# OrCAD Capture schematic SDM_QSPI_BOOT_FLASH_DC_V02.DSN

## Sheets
1 Cover: title: SDM QSPI Boot Flash Daughter Card; rev: 0.1; note: 150-0330636-A1     (6XX-44489R)
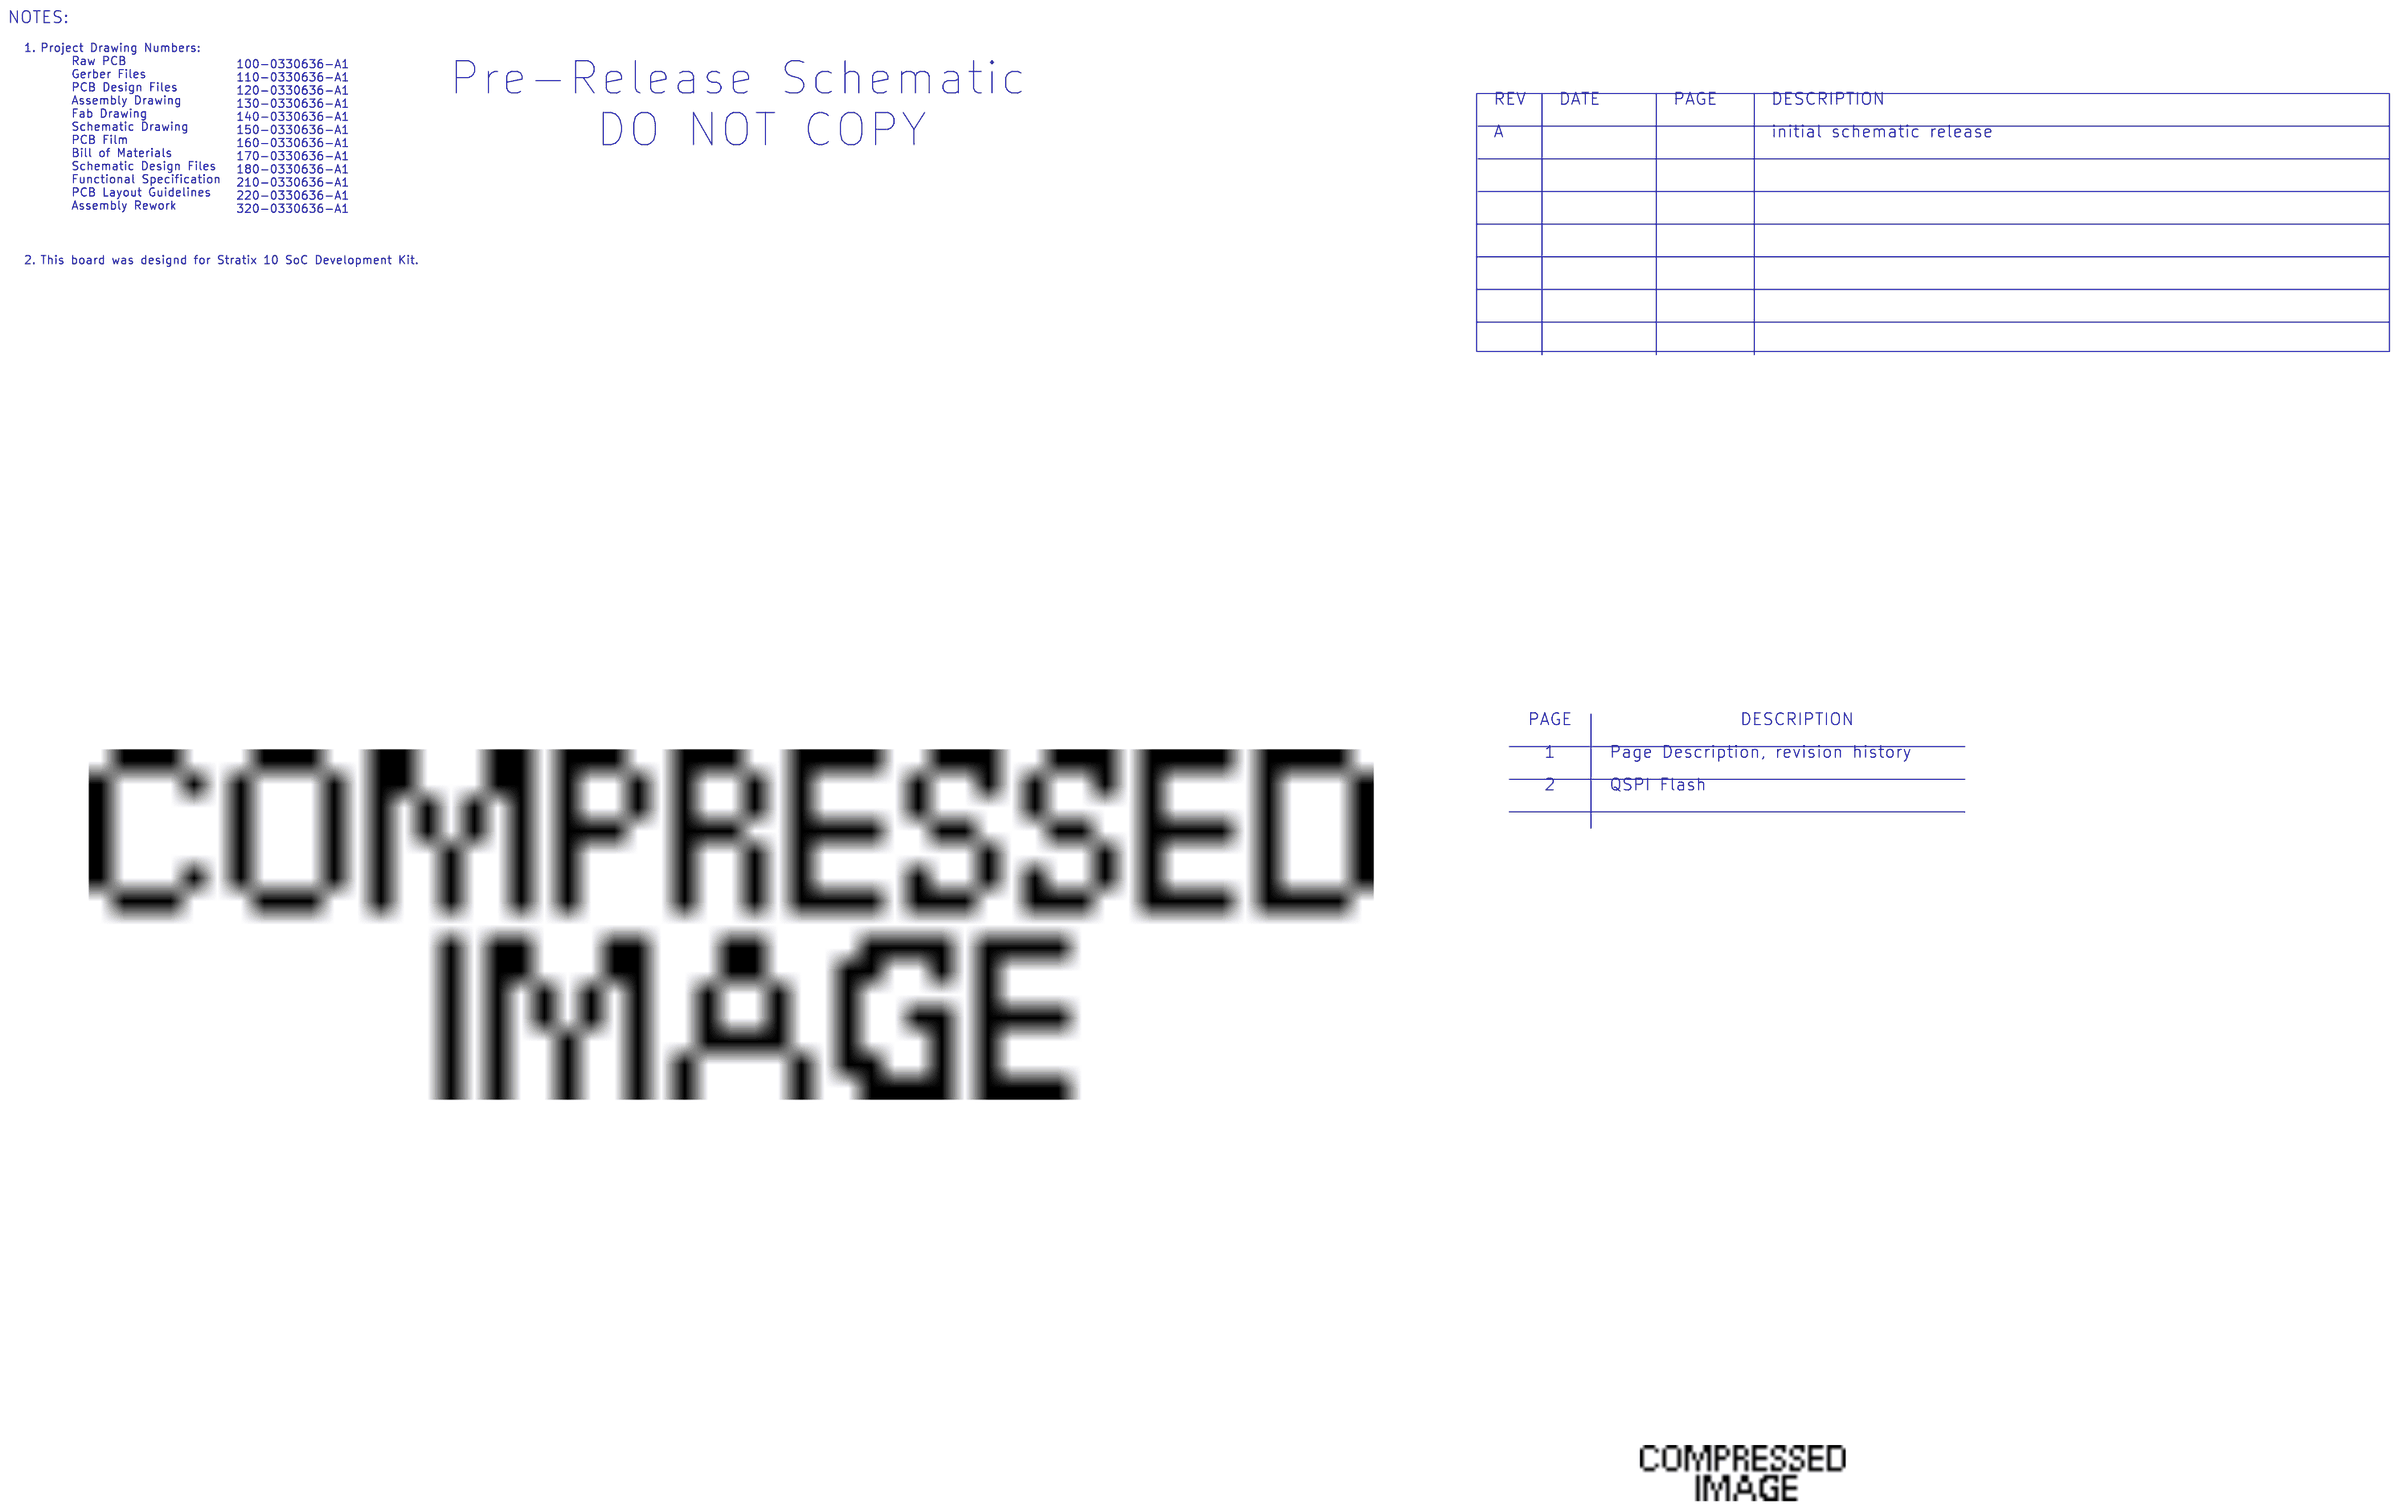
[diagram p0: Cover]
2 QSPI Flash: size B
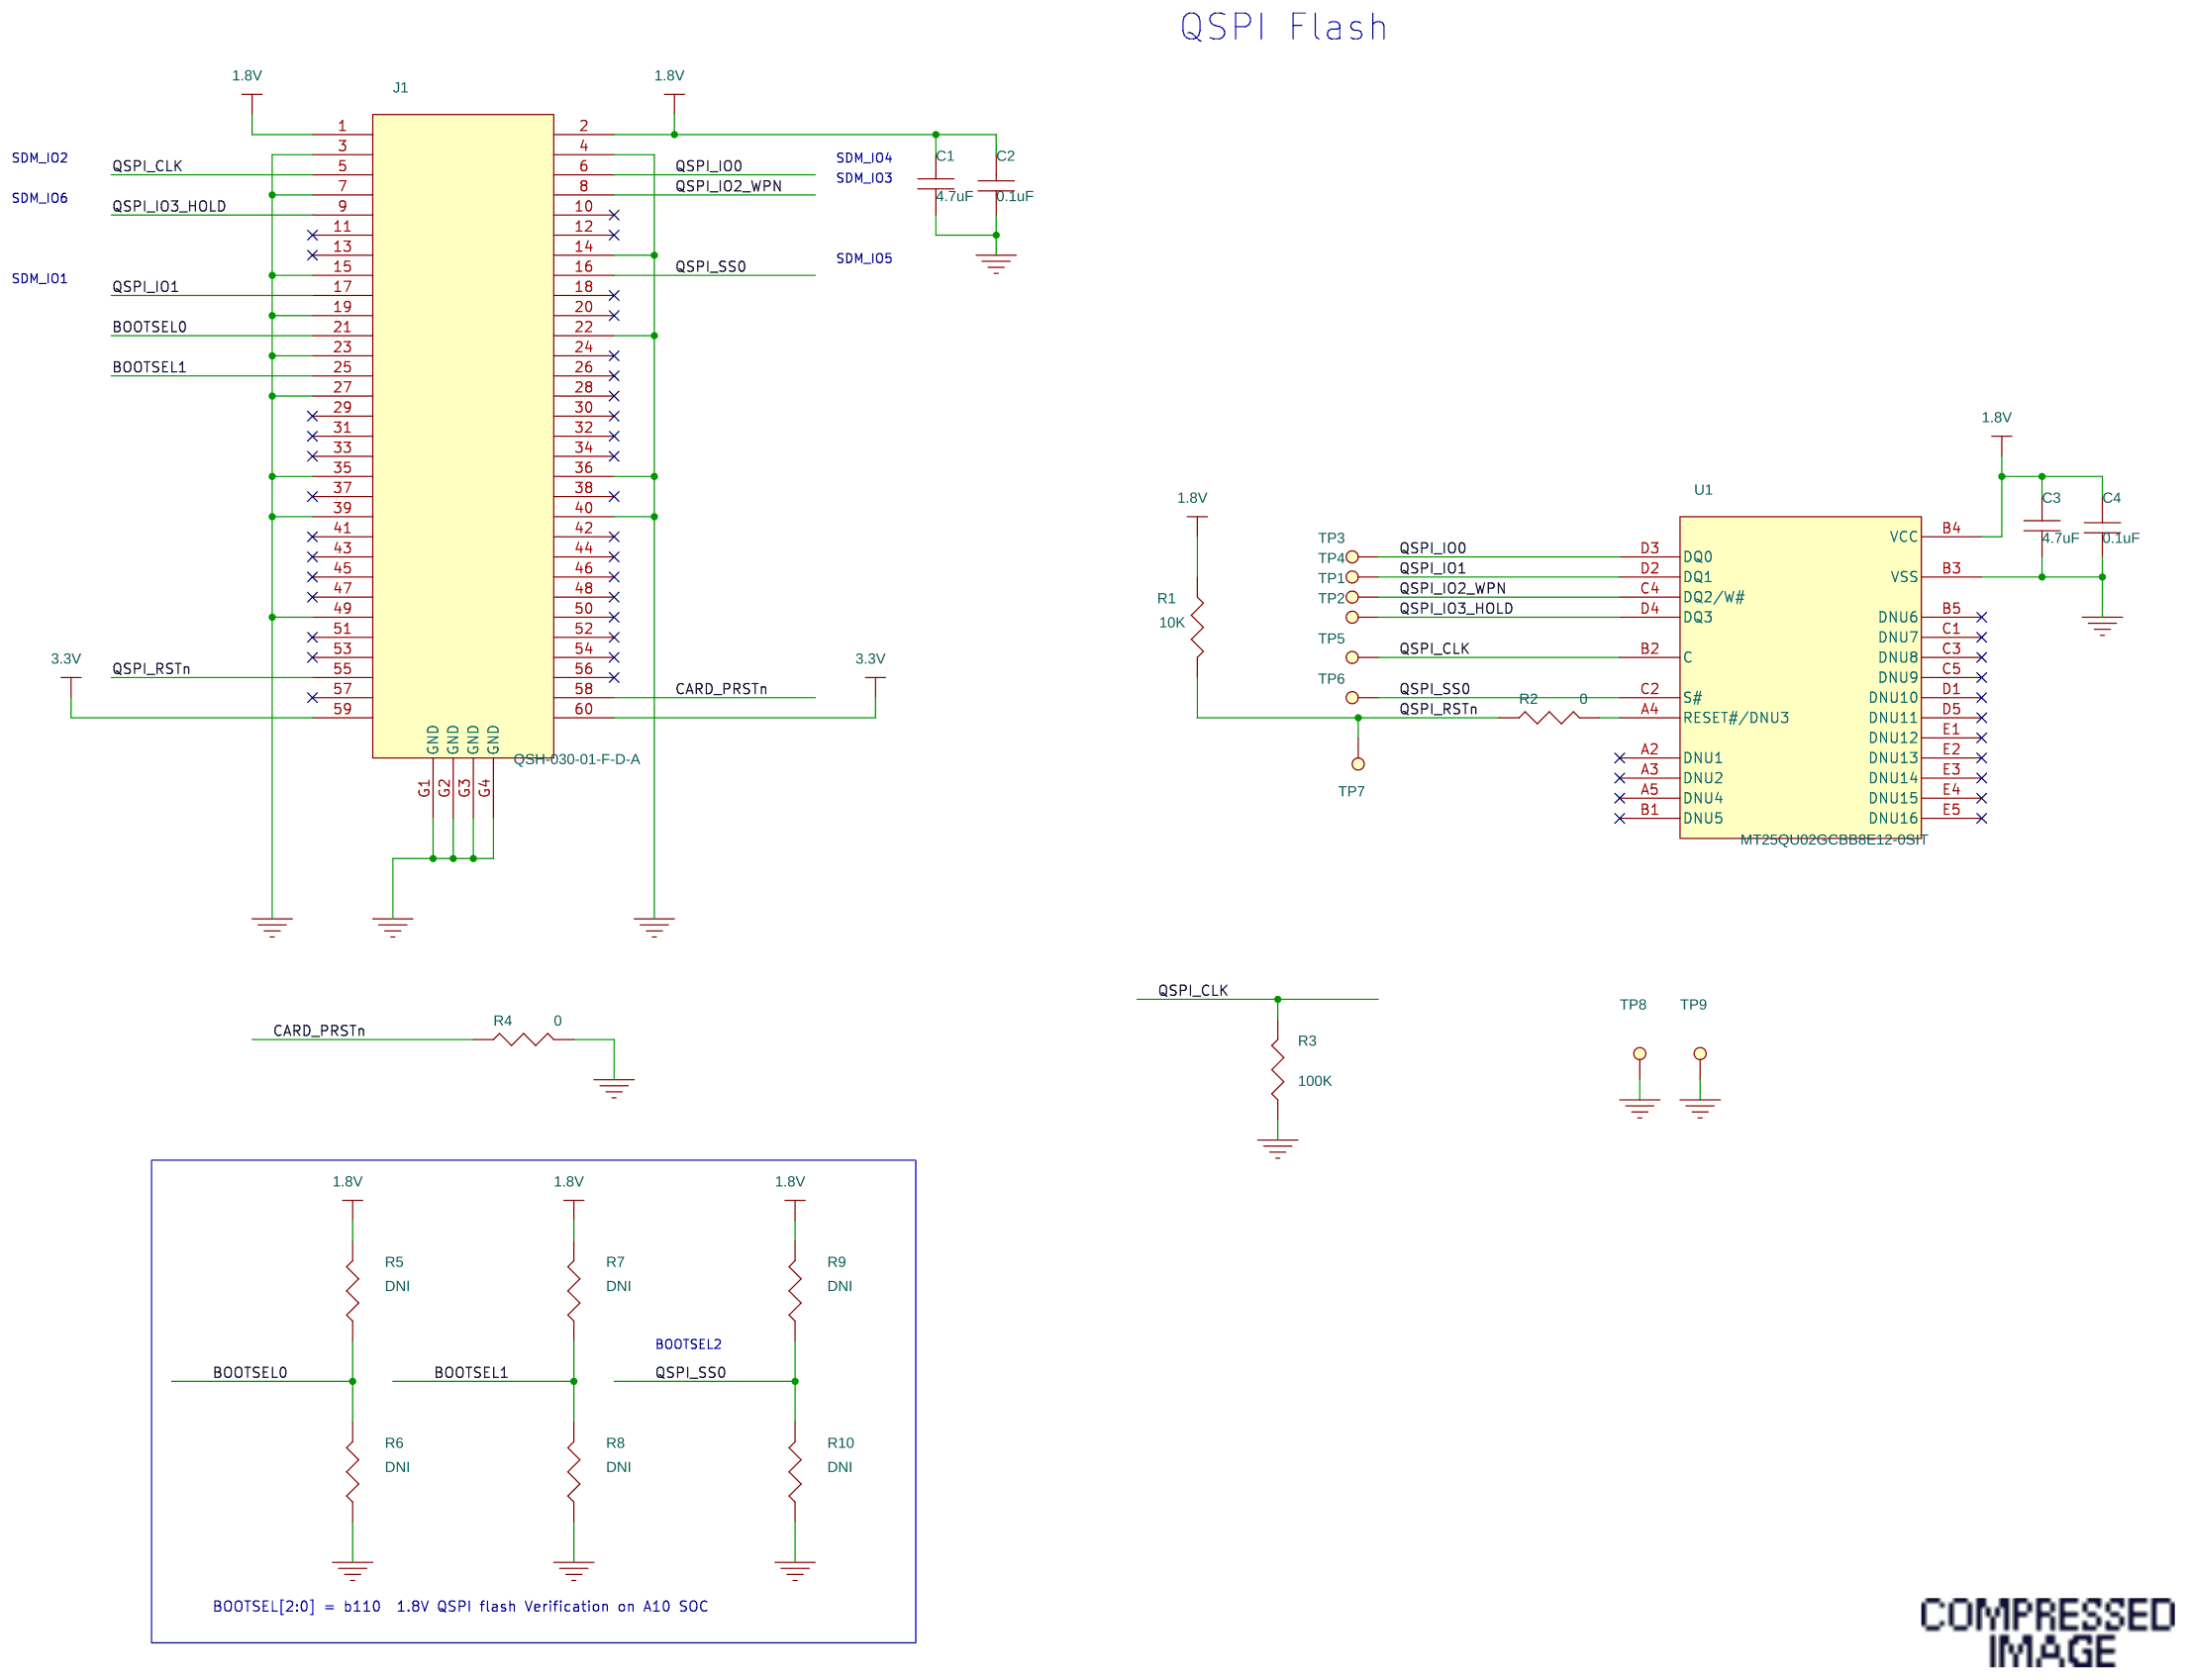
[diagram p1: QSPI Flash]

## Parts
C1  4.7uF  [0805]
C2  0.1uF  [0402]
C3  4.7uF  [0805]
C4  0.1uF  [0402]
J1  QSH-030-01-F-D-A  [QSH-030-01-F-D-A]
R1  10K  [0402]
R2  0  [0402]
R3  100K  [0402]
R4  0  [0402]
R5  DNI  [0402]
R6  DNI  [0402]
R7  DNI  [0402]
R8  DNI  [0402]
R9  DNI  [0402]
R10  DNI  [0402]
TP1  VIA_1  [TP_020RD_SMT]
TP2  VIA_1  [TP_020RD_SMT]
TP3  VIA_1  [TP_020RD_SMT]
TP4  VIA_1  [TP_020RD_SMT]
TP5  VIA_1  [TP_020RD_SMT]
TP6  VIA_1  [TP_020RD_SMT]
TP7  VIA_1  [TP_020RD_SMT]
TP8  VIA_1  [TP_020RD_SMT]
TP9  VIA_1  [TP_020RD_SMT]
U1  MT25QU02GCBB8E12-0SIT  [TBGA_24]

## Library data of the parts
C1 C3 = CAP: CAP - CER, 4.7UF, 16V, X5R, 0805; Item Num: P03-15412R; Manufacturer: Murata; Manufacturer Part Num: GRM21BR61C475KA88L; Num Pins: 2; RoHS Compliant: RoHS Compliant
C2 C4 = CAP: CAP CER 0.1UF 25V 20% X7R 0402; Item Num: P03-17618R; LIFECYCLE_PHASE: Active; Manufacturer: TDK Electronics; Manufacturer Part Num: C1005X7R1E104M; Price: 0; RoHS Compliant: RoHS Compliant
J1 = QSH-030-01-F-D-A: RoHS Compliant: RoHS Compliant
R1 = RESISTOR: RES,10.0K OHMS,1.0%,1/16W, 0402; Item Num: P02-11364R; Manufacturer: Panasonic; Manufacturer Part Num: ERJ-2RKF1002X; Price: 0; RoHS Compliant: RoHS Compliant
R2 R4 = RESISTOR: RES ZERO OHM 1/16W 5% 0402 SMD; Altera Part No.: P02-14020R; Item Num: P02-14020R; Lead Free Status: No; Manufacturer: Panasonic; Manufacturer Part Num: ERJ-2GE0R00X; Num Pins: 2; Part Class: RESISTORS; RoHS Compliant: Yes; Tolerance: 5%
R3 = RES_100K_OHM_1.0%_1_16W_0402: RoHS Compliant: RoHS Compliant
R5 R7 R9 = RESISTOR: RES,10.0K OHMS,1.0%,1/16W, 0402; AGILE_LINK: http://sj-agile9app/Agile/PLMServlet?action=OpenEmailObject&classid=10000&objid=146548997; Item Num: P02-11364R; LIFECYCLE_PHASE: Active; Lead Free Status: No; MFR_LIFECYCLE: Active; Manufacturer: Panasonic; Manufacturer Part Num: ERJ-2RKF1002X; Num Pins: 2; PART_SUBCLASS: RESISTORS; POWER: 1/16W; RESISTANCE: 10K; RoHS Compliant: Yes; TOLERANCE: +/-1%
R6 R8 R10 = RESISTOR: RES,1.00K OHMS,1.0%,1/16W,0402; Item Num: P02-11372R; Lead Free Status: No; Manufacturer: Panasonic; Manufacturer Part Num: ERJ-2RKF1001X; Num Pins: 2; Part Class: Resistors
TP1-TP9 = VIA_1
U1 = MT25QU01GBBA8E12-0SIT: MEM - 2GBIT, MULTI-IO SERIAL NOR FLASH, 1.8V, TBGA24; Item Num: P01-18099R; RoHS Compliant: RoHS Compliant

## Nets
1.8V: C1.1 C2.2 C3.1 C4.2 J1.1 J1.2 R1.2 R5.2 R7.2 R9.2 U1.B4(VCC)
3.3V: J1.59 J1.60
GND: C1.2 C2.1 C3.2 C4.1 J1.3 J1.4 J1.7 J1.14 J1.15 J1.19 J1.22 J1.23 J1.27 J1.35 J1.36 J1.39 J1.40 J1.49 J1.G1(GND) J1.G2(GND) J1.G3(GND) J1.G4(GND) R3.1 R4.2 R6.1 R8.1 R10.1 TP8.1(TP) TP9.1(TP) U1.B3(VSS)
BOOTSEL0: J1.21 R5.1 R6.2
BOOTSEL1: J1.25 R7.1 R8.2
CARD_PRSTn: J1.58 R4.1
QSPI_CLK: J1.5 R3.2 TP5.1(TP) U1.B2(C)
QSPI_IO0: J1.6 TP3.1(TP) U1.D3(DQ0)
QSPI_IO1: J1.17 TP4.1(TP) U1.D2(DQ1)
QSPI_IO2_WPN: J1.8 TP1.1(TP) U1.C4(DQ2/W#)
QSPI_IO3_HOLD: J1.9 TP2.1(TP) U1.D4(DQ3)
QSPI_RSTn: J1.55 R1.1 R2.1 TP7.1(TP)
QSPI_SS0: J1.16 R9.1 R10.2 TP6.1(TP) U1.C2(S#)
N16547222: R2.2 U1.A4(RESET#/DNU3)

Not connected (* = marked no-connect by the designer): J1 10* 11* 12* 13* 18* 20* 24* 26* 28* 29* 30* 31* 32* 33* 34* 37* 38* 41* 42* 43* 44* 45* 46* 47* 48* 50* 51* 52* 53* 54* 56* 57*; U1 A2(DNU1)* A3(DNU2)* A5(DNU4)* B1(DNU5)* B5(DNU6)* C1(DNU7)* C3(DNU8)* C5(DNU9)* D1(DNU10)* D5(DNU11)* E1(DNU12)* E2(DNU13)* E3(DNU14)* E4(DNU15)* E5(DNU16)*

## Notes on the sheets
sheet 1
- NOTES:
- 1.
- Project Drawing Numbers:
       Raw PCB
       Gerber Files
       PCB Design Files
       Assembly Drawing
       Fab Drawing
       Schematic Drawing
       PCB Film
       Bill of Materials
       Schematic Design Files
       Functional Specification
       PCB Layout Guidelines
       Assembly Rework
- 100-0330636-A1
  110-0330636-A1
  120-0330636-A1
  130-0330636-A1
  140-0330636-A1
  150-0330636-A1
  160-0330636-A1
  170-0330636-A1
  180-0330636-A1
  210-0330636-A1
  220-0330636-A1
  320-0330636-A1
- Pre-Release Schematic
        DO NOT COPY
- REV
- DATE
- PAGE
- DESCRIPTION
- A
- initial schematic release
- 2.
- This board was designd for Stratix 10 SoC Development Kit.
- PAGE
- DESCRIPTION
- 1
- Page Description, revision history
- 2
- QSPI Flash
sheet 2
- QSPI Flash
- SDM_IO2
- SDM_IO4
- SDM_IO3
- SDM_IO6
- SDM_IO1
- SDM_IO5
- BOOTSEL2
- BOOTSEL[2:0] = b110  1.8V QSPI flash Verification on A10 SOC
